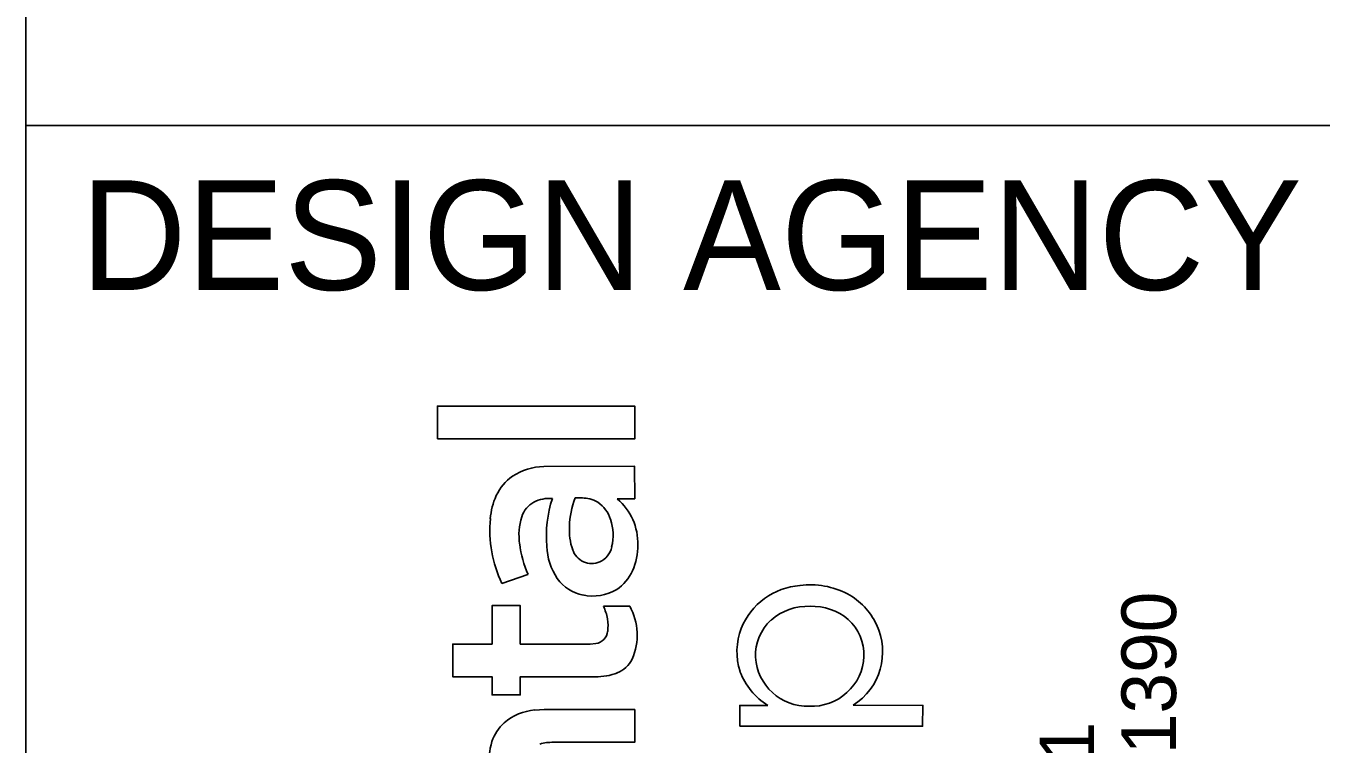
# Model space of a CAD drawing. Extents: x -0.2 to 34, y 0 to 22.
# Drawn here: x 32 to 33.182, y 3.936 to 4.591 of the extents above; entities that cross this region are included whole.
import ezdxf

# ---------------------------------------------------------------- set-up
doc = ezdxf.new("R2010")
doc.units = 0
doc.layers.add('SH_Border', color=7, linetype='Continuous')
doc.layers.add('SH_Data', color=7, linetype='Continuous')

msp = doc.modelspace()

# ---------------------------------------------------------------- linework, layer by layer
at = {"layer": 'SH_Border'}
for p, q in [((32, 0.5), (32, 21.5)), ((32, 4.5), (33.5, 4.5))]:
    msp.add_line(p, q, dxfattribs=at)
at = {"layer": 'SH_Data'}
for p, q in [((32.3756, 4.2141), (32.3756, 4.244)), ((32.3756, 4.244), (32.5557, 4.244)), ((32.5557, 4.244), (32.5557, 4.2141)), ((32.5557, 4.2141), (32.3756, 4.2141)), ((32.4727, 4.189), (32.5555, 4.1892)), ((32.5555, 4.1892), (32.5557, 4.1596)), ((32.5557, 4.1596), (32.5397, 4.1596)), ((32.4582, 4.0904), (32.4343, 4.0823)), ((32.4254, 4.027), (32.4255, 4.0621)), ((32.4255, 4.0621), (32.4511, 4.0621)), ((32.4511, 4.0621), (32.4512, 4.027)), ((32.527, 4.0616), (32.5511, 4.0616)), ((32.3896, 3.9972), (32.3896, 4.027)), ((32.3896, 4.027), (32.4254, 4.027)), ((32.4512, 4.027), (32.515, 4.027)), ((32.515, 4.027), (32.52, 4.0275)), ((32.4254, 3.9972), (32.3896, 3.9972)), ((32.4254, 3.9807), (32.4254, 3.9972)), ((32.5197, 3.9972), (32.4511, 3.9972)), ((32.4511, 3.9972), (32.4511, 3.9807)), ((32.4511, 3.9807), (32.4254, 3.9807)), ((32.4644, 3.9669), (32.4729, 3.9673)), ((32.4729, 3.9673), (32.5557, 3.9673)), ((32.5557, 3.9673), (32.5557, 3.9375)), ((32.6515, 3.9521), (32.6515, 3.9711)), ((32.6515, 3.9711), (32.6771, 3.9711)), ((32.7549, 3.9713), (32.8186, 3.9711)), ((32.8186, 3.9711), (32.8184, 3.9521)), ((32.8184, 3.9521), (32.6515, 3.9521)), ((32.5557, 3.9375), (32.4814, 3.9375))]:
    msp.add_line(p, q, dxfattribs=at)
msp.add_lwpolyline([(32.3756, 4.2141), (32.3756, 4.244), (32.5557, 4.244), (32.5557, 4.2141)], close=True, dxfattribs=at)
for points in [[(32.4727, 4.189), (32.5555, 4.1892), (32.5557, 4.1596)], [(32.5557, 4.1596), (32.5397, 4.1596)], [(32.4582, 4.0904), (32.4343, 4.0823)], [(32.5197, 3.9972), (32.4511, 3.9972), (32.4511, 3.9807), (32.4254, 3.9807), (32.4254, 3.9972), (32.3896, 3.9972), (32.3896, 4.027), (32.4254, 4.027), (32.4255, 4.0621), (32.4511, 4.0621), (32.4512, 4.027), (32.515, 4.027), (32.52, 4.0275)], [(32.527, 4.0616), (32.5511, 4.0616)], [(32.4644, 3.9669), (32.4729, 3.9673), (32.5557, 3.9673), (32.5557, 3.9375), (32.4814, 3.9375)], [(32.7549, 3.9713), (32.8186, 3.9711), (32.8184, 3.9521), (32.6515, 3.9521)], [(32.6515, 3.9521), (32.6515, 3.9711), (32.6771, 3.9711)]]:
    msp.add_lwpolyline(points, dxfattribs=at)
for centre, radius, start, end in [((32.4745, 4.1326), 0.0565, 91.8942, 122.6317), ((32.4745, 4.1326), 0.0565, 91.8942, 122.6317), ((32.4685, 4.1447), 0.043, 124.537, 155.6594), ((32.4685, 4.1447), 0.043, 124.537, 155.6594), ((32.4882, 4.1361), 0.0646, 155.9764, 175.3149), ((32.4882, 4.1361), 0.0646, 155.9764, 175.3149), ((32.4753, 4.1356), 0.024, 119.4252, 161.6629), ((32.4753, 4.1356), 0.024, 119.4252, 161.6629), ((32.4779, 4.1278), 0.0321, 85.3802, 116.6222), ((32.4779, 4.1278), 0.0321, 85.3802, 116.6222), ((32.5879, 4.1251), 0.1129, 162.0821, 184.5285), ((32.5879, 4.1251), 0.1129, 162.0821, 184.5285), ((32.5801, 4.1313), 0.0841, 159.8366, 178.0362), ((32.5801, 4.1313), 0.0841, 159.8366, 178.0362), ((32.5051, 4.1074), 0.053, 79.6696, 94.2322), ((32.5051, 4.1074), 0.053, 79.6696, 94.2322), ((32.5089, 4.1364), 0.0238, 56.8913, 76.2149), ((32.5089, 4.1364), 0.0238, 56.8913, 76.2149), ((32.5052, 4.1318), 0.0297, 17.5984, 55.7282), ((32.5052, 4.1318), 0.0297, 17.5984, 55.7282), ((32.5055, 4.1191), 0.0529, 358.0746, 49.762), ((32.5055, 4.1191), 0.0529, 358.0746, 49.762), ((32.5364, 4.1308), 0.113, 174.6101, 205.3899), ((32.5364, 4.1308), 0.113, 174.6101, 205.3899), ((32.5076, 4.1265), 0.0576, 163.1369, 188.1675), ((32.5076, 4.1265), 0.0576, 163.1369, 188.1675), ((32.4916, 4.1264), 0.0443, 345.9408, 18.9919), ((32.4916, 4.1264), 0.0443, 345.9408, 18.9919), ((32.5466, 4.1303), 0.0506, 175.5903, 199.8857), ((32.5466, 4.1303), 0.0506, 175.5903, 199.8857), ((32.5473, 4.1297), 0.0973, 186.7598, 203.7981), ((32.5473, 4.1297), 0.0973, 186.7598, 203.7981), ((32.5328, 4.1187), 0.0575, 182.5676, 213.7144), ((32.5328, 4.1187), 0.0575, 182.5676, 213.7144), ((32.5152, 4.1199), 0.0199, 295.2883, 347.4639), ((32.5152, 4.1199), 0.0199, 295.2883, 347.4639), ((32.5019, 4.1168), 0.0566, 336.016, 0.5951), ((32.5019, 4.1168), 0.0566, 336.016, 0.5951), ((32.5164, 4.1189), 0.0184, 198.2844, 293.3081), ((32.5164, 4.1189), 0.0184, 198.2844, 293.3081), ((32.5175, 4.1097), 0.0394, 303.4436, 336.18), ((32.5175, 4.1097), 0.0394, 303.4436, 336.18), ((32.5149, 4.1078), 0.0366, 215.0668, 259.8133), ((32.5149, 4.1078), 0.0366, 215.0668, 259.8133), ((32.7108, 4.0182), 0.0624, 93.9866, 158.3119), ((32.7108, 4.0182), 0.0624, 93.9866, 158.3119), ((32.7156, 4.0065), 0.0746, 62.6889, 97.0135), ((32.7156, 4.0065), 0.0746, 62.6889, 97.0135), ((32.5175, 4.1131), 0.0423, 257.5256, 300.882), ((32.5175, 4.1131), 0.0423, 257.5256, 300.882), ((32.7212, 4.0191), 0.0608, 25.0657, 61.9602), ((32.7212, 4.0191), 0.0608, 25.0657, 61.9602), ((32.4863, 4.042), 0.0452, 10.1545, 25.723), ((32.4863, 4.042), 0.0452, 10.1545, 25.723), ((32.503, 4.0351), 0.0549, 336.589, 28.8991), ((32.503, 4.0351), 0.0549, 336.589, 28.8991), ((32.7138, 4.0102), 0.0513, 87.8965, 131.1812), ((32.7138, 4.0102), 0.0513, 87.8965, 131.1812), ((32.7175, 4.0102), 0.0513, 49.9089, 92.0363), ((32.7175, 4.0102), 0.0513, 49.9089, 92.0363), ((32.4957, 4.0436), 0.0356, 351.914, 10.2059), ((32.4957, 4.0436), 0.0356, 351.914, 10.2059), ((32.7092, 4.0167), 0.0434, 132.3289, 182.0949), ((32.7092, 4.0167), 0.0434, 132.3289, 182.0949), ((32.7215, 4.0173), 0.0433, 358.0487, 47.9447), ((32.7215, 4.0173), 0.0433, 358.0487, 47.9447), ((32.7245, 4.02), 0.0574, 301.9776, 25.6418), ((32.7245, 4.02), 0.0574, 301.9776, 25.6418), ((32.5184, 4.04), 0.0126, 277.6142, 353.7918), ((32.5184, 4.04), 0.0126, 277.6142, 353.7918), ((32.707, 4.0202), 0.0581, 158.656, 198.171), ((32.707, 4.0202), 0.0581, 158.656, 198.171), ((32.5291, 4.0261), 0.0275, 292.6889, 332.0598), ((32.5291, 4.0261), 0.0275, 292.6889, 332.0598), ((32.7135, 4.0181), 0.0478, 183.5974, 271.7045), ((32.7135, 4.0181), 0.0478, 183.5974, 271.7045), ((32.7172, 4.018), 0.0477, 267.3149, 357.4019), ((32.7172, 4.018), 0.0477, 267.3149, 357.4019), ((32.5209, 4.0486), 0.0514, 268.6727, 291.5235), ((32.5209, 4.0486), 0.0514, 268.6727, 291.5235), ((32.7103, 4.0243), 0.0627, 200.8399, 238.0162), ((32.7103, 4.0243), 0.0627, 200.8399, 238.0162), ((32.4687, 3.9172), 0.0499, 94.9706, 130.2248), ((32.4687, 3.9172), 0.0499, 94.9706, 130.2248), ((32.4635, 3.9255), 0.0402, 132.2238, 161.6823), ((32.4635, 3.9255), 0.0402, 132.2238, 161.6823), ((32.4787, 3.9211), 0.056, 162.274, 187.7917), ((32.4787, 3.9211), 0.056, 162.274, 187.7917), ((32.4811, 3.8915), 0.046, 89.6051, 105.3303), ((32.4811, 3.8915), 0.046, 89.6051, 105.3303)]:
    msp.add_arc(centre, radius, start, end, dxfattribs=at)

# ---------------------------------------------------------------- texts
msp.add_text('DESIGN AGENCY', height=0.1, dxfattribs=at).set_placement((32.05, 4.35))
for s, p in [('800.835.1390', (33.0497, 3.6671)), ('450 GRANT ST., AKRON, OH  44311', (32.9749, 2.8374))]:
    msp.add_text(s, height=0.049846, rotation=90, dxfattribs=at).set_placement(p)

doc.saveas('drawing.dxf')
